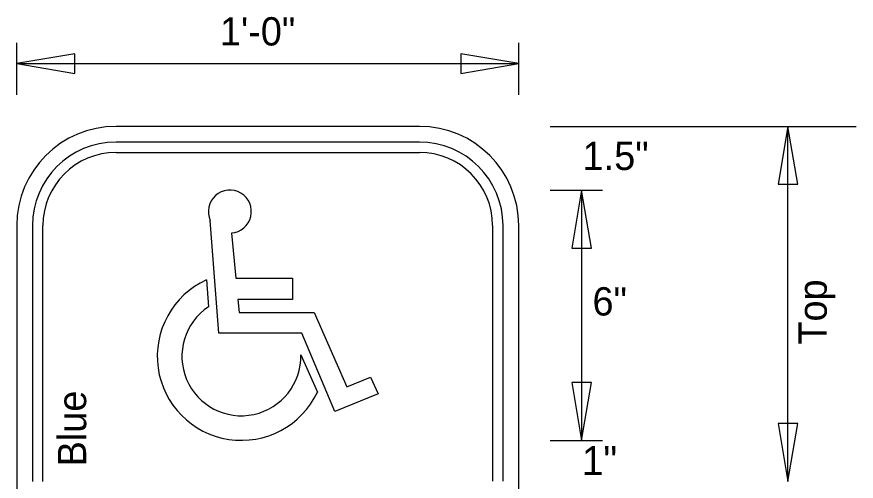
# Model space of a CAD drawing. Extents: x 0 to 770, y 0 to 495.
# Drawn here: x 274.2 to 378, y 418.9 to 476.4 of the extents above; entities that cross this region are included whole.
import ezdxf

# ---------------------------------------------------------------- set-up
doc = ezdxf.new("R2010")
doc.units = 0
for name, color, linetype in [('Default', 7, 'Continuous'), ('Dimension', 7, 'Continuous'), ('GSDims', 7, 'Continuous'), ('TextStructures', 7, 'Continuous')]:
    doc.layers.add(name, color=color, linetype=linetype)

msp = doc.modelspace()

# ---------------------------------------------------------------- linework, layer by layer
at = {"layer": 'Default'}
for p, q in [((324.01, 462.81), (286.52, 462.81)), ((324.01, 460.87), (286.52, 460.87)), ((286.52, 459.58), (324.01, 459.58)), ((274.24, 450.53), (274.24, 382.03)), ((276.18, 450.53), (276.18, 418.87)), ((277.47, 418.87), (277.47, 450.53)), ((333.05, 450.53), (333.05, 418.91)), ((334.35, 418.92), (334.35, 450.53)), ((336.28, 382.03), (336.28, 450.53)), ((297.69, 443.82), (297.93, 440.48)), ((297.69, 443.82), (297.69, 443.82)), ((297.69, 443.82), (297.93, 440.48)), ((297.69, 443.82), (297.69, 443.82)), ((297.69, 443.82), (297.93, 440.48)), ((297.69, 443.82), (297.69, 443.82)), ((309.35, 434.55), (311.4, 429.92)), ((309.35, 434.55), (311.4, 429.92)), ((309.35, 434.55), (311.4, 429.92))]:
    msp.add_line(p, q, dxfattribs=at)
for points in [[(313.56, 427.52), (309.46, 437.22), (299.21, 437.22), (298.15, 451.16)], [(313.56, 427.52), (309.46, 437.22), (299.21, 437.22), (298.15, 451.16)], [(313.56, 427.52), (309.46, 437.22), (299.21, 437.22), (298.15, 451.16)], [(300.77, 449.61), (301.31, 444.01), (308.31, 444.01), (308.31, 441.39), (301.56, 441.39), (301.72, 439.8), (311, 439.8), (315.05, 430.6), (317.97, 431.78), (318.92, 429.74), (313.56, 427.52)], [(300.77, 449.61), (301.31, 444.01), (308.31, 444.01), (308.31, 441.39), (301.56, 441.39), (301.72, 439.8), (311, 439.8), (315.05, 430.6), (317.97, 431.78), (318.92, 429.74), (313.56, 427.52)], [(300.77, 449.61), (301.31, 444.01), (308.31, 444.01), (308.31, 441.39), (301.56, 441.39), (301.72, 439.8), (311, 439.8), (315.05, 430.6), (317.97, 431.78), (318.92, 429.74), (313.56, 427.52)]]:
    msp.add_lwpolyline(points, dxfattribs=at)
for centre, radius, start, end in [((286.52, 450.53), 12.28, 90, 180), ((324.01, 450.53), 12.28, 0, 90), ((286.52, 450.53), 10.34, 90, 180), ((324.01, 450.53), 10.34, 0, 90), ((286.52, 450.53), 9.05, 90, 180), ((324.01, 450.53), 9.05, 0, 90), ((300.58, 452.27), 2.66, 274.0338, 204.3912), ((300.58, 452.27), 2.66, 274.0338, 204.3912), ((300.58, 452.27), 2.66, 274.0338, 204.3912), ((302, 434.36), 10.39, 114.5109, 334.7279), ((302, 434.36), 10.39, 114.5109, 334.7279), ((302, 434.36), 10.39, 114.5109, 334.7279), ((302, 434.36), 7.35, 123.5699, 1.485), ((302, 434.36), 7.35, 123.5699, 1.485), ((302, 434.36), 7.35, 123.5699, 1.485)]:
    msp.add_arc(centre, radius, start, end, dxfattribs=at)
at = {"layer": 'Dimension'}
for points in [[(274.24, 470.57), (281.42, 469.35), (281.42, 471.78)], [(336.28, 470.57), (329.11, 471.78), (329.11, 469.35)], [(369.55, 462.81), (368.34, 455.64), (370.77, 455.64)], [(344.04, 454.93), (342.83, 447.75), (345.26, 447.75)], [(344.04, 423.96), (345.26, 431.14), (342.83, 431.14)], [(369.55, 418.86), (370.77, 426.04), (368.34, 426.04)]]:
    msp.add_lwpolyline(points, close=True, dxfattribs=at)
at = {"layer": 'GSDims'}
for p, q in [((274.24, 466.69), (274.24, 473.15)), ((336.28, 466.69), (336.28, 473.15)), ((274.24, 470.57), (336.28, 470.57)), ((340.16, 462.81), (346.63, 462.81)), ((346.63, 462.81), (378, 462.81)), ((369.55, 418.86), (369.55, 462.81)), ((340.16, 454.93), (346.63, 454.93)), ((340.16, 454.93), (346.63, 454.93)), ((344.04, 454.93), (344.04, 423.96)), ((340.16, 423.96), (346.63, 423.96)), ((340.16, 423.96), (346.63, 423.96))]:
    msp.add_line(p, q, dxfattribs=at)

# ---------------------------------------------------------------- texts
at = {"layer": 'TextStructures'}
for s, height, p in [('1\'-0"', 3.5, (299.35, 472.81)), ('1.5"', 3.5, (344.18, 457.41)), ('6"', 3.5, (345.4, 439.41)), ('1"', 3.578, (344.09, 419.67))]:
    msp.add_text(s, height=height, dxfattribs=at).set_placement(p)
for s, p in [('Top', (374.36, 435.81)), ('Blue', (282.82, 420.75))]:
    msp.add_text(s, height=3.5, rotation=90, dxfattribs=at).set_placement(p)

doc.saveas('drawing.dxf')
